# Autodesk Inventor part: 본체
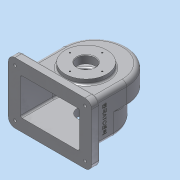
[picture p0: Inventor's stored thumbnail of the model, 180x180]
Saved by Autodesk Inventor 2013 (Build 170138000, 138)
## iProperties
Created: 2017-11
Part Number: 본체
Material: 알루미늄 6061
Document SubType Name: Modeling
Designer: dgall
Density: 2.71 g/cm^3
Mass: 1079.49 g
Surface Area: 1182.07 cm^2
Volume: 398.334 cm^3
Author: dgall
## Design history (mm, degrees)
sketch "스케치1"
  geometry: L1 (-58, 0)-(-58, -80); L2 (-58, -80)-(58, -80); L3 (58, -80)-(58, 0); A1 r 58 centre (0, 0) between (-58, 0) and (58, 0); 1 further point
  constraints: 6 end point, 2 point on circle, 2 tangent, 2 vertical, 1 centre point, 1 coincident, 1 perpendicular
  dimensions: "d0" = 58 radius of A1; "d1" = 80 distance of L1.start L1.end
extrude "돌출1" new body sketch "스케치1" distance "d2" = 38; taper "d3" = 0 deg
sketch "스케치2"
  geometry: L1 (58, 0)-(58, -80) reference; L2 (-58, -80)-(-58, 0) reference; L3 (58, -80)-(-58, -80) reference; L4 (-58, -23)-(-58, -80); L5 (58, -80)-(-58, -80); L6 (58, -80)-(58, -23); A1 r 58 centre (0, 0) between (58, 0) and (-58, 0) reference; A2 r 58 centre (0, -23) between (10.724, -80) and (-10.724, -80)
  constraints: 6 end point, 4 point on circle, 4 point on line, 2 collinear, 1 centre point, 1 vertical alignment
  dimensions: "d4" = 58 radius of A2; "d5" = 57 distance from line of L3 A2.centre
extrude "돌출2" join sketch "스케치2" distance "d6" = 38; taper "d7" = 0 deg
feature "쉘1" dims "d8" = 5
sketch "스케치3"
  geometry: L1 (-58, -80)-(58, -80) reference; C1 r 37.5 at (0, -15); A1 r 58 centre (0, 0) between (58, 0) and (-58, 0) reference
  constraints: 1 centre point, 1 vertical alignment
  dimensions: "d9" = 75 diameter of C1; "d10" = 65 distance from line of L1 C1.centre
extrude "돌출3" join sketch "스케치3" distance "d11" = 9; taper "d12" = 0 deg
sketch "스케치4"
  geometry: L1 (-58, -80)-(58, -80) reference; C1 r 31 at (0, -15); A1 r 58 centre (0, -23) between (58, -23) and (-58, -23) reference; 1 further point
  constraints: 1 centre point, 1 vertical alignment
  dimensions: "d13" = 62 diameter of C1; "d14" = 65 distance from line of L1 C1.centre
extrude "돌출4" join sketch "스케치4" distance "d15" = 10; taper "d16" = 0 deg
sketch "스케치5"
  geometry: C1 r 37.5 at (0, 0) reference; C2 r 16 at (0, 0); 1 further point
  constraints: 1 centre point, 1 coincident
  dimensions: "d17" = 32 diameter of C2
extrude "돌출5" cut sketch "스케치5" stored distance "d18" = 10; taper "d19" = 0 deg
sketch "스케치6" dims "d20" = 58
  geometry: C1 r 37.5 at (0, 0) reference; 3 further points
  constraints: 2 vertical alignment, 1 coincident, 2 other
hole "구멍1" sketch "스케치6" at (0, 29) diameter "d21" = 2.459; stored, may be unused: countersink angle "d25" = 90 deg, drill point angle "d27" = 118 deg; dims "d22" = 6, "d23" = 4, "d24" = 2, "d26" = 8
sketch "스케치7" dims "d31" = 52
  geometry: C1 r 16 at (0, 0) reference; C2 r 31 at (0, 0) reference; 3 further points
  constraints: 2 vertical alignment, 1 coincident, 2 other
hole "구멍2" sketch "스케치7" at (0, 26) diameter "d32" = 2.459; stored, may be unused: countersink angle "d36" = 90 deg, drill point angle "d38" = 118 deg; dims "d33" = 6, "d34" = 4, "d35" = 2, "d37" = 8
chamfer "모따기1" distance "d42" = 1; stored, may be unused: second distance "d43" = 2, angle "d44" = 45 deg
sketch "스케치8"
  geometry: L1 (-17, 17)-(133, 17); L2 (133, 17)-(133, -93); L3 (133, -93)-(-17, -93); L4 (-17, -93)-(-17, 17); L5 (116, -38)-(0, -38) reference; L6 (0, 0)-(116, 0); L7 (116, 0)-(116, -76); L8 (116, -76)-(0, -76); L9 (0, -76)-(0, 0); 4 further points
  constraints: 16 end point, 4 parallel, 3 midpoint, 2 horizontal, 2 perpendicular, 1 horizontal alignment, 1 vertical alignment
  dimensions: "d45" = 150 distance of L1.start L1.end; "d47" = 110 distance of L1.end L2.end
extrude "돌출6" join sketch "스케치8" distance "d48" = 15; taper "d49" = 0 deg
fillet "모깎기1" dims "d50" = 12
sketch "스케치9"
  geometry: A1 r 12 centre (-5, -5) between (-17, -5) and (-5, -17) reference; A2 r 12 centre (121, -5) between (121, -17) and (133, -5) reference; A3 r 12 centre (121, 81) between (133, 81) and (121, 93) reference; A4 r 12 centre (-5, 81) between (-5, 93) and (-17, 81) reference; 5 further points
  constraints: 4 coincident
hole "구멍3" sketch "스케치9" at (-5, 81), (-5, -5), (121, -5), (121, 81) diameter "d51" = 5; stored, may be unused: countersink angle "d55" = 90 deg, drill point angle "d57" = 118 deg; dims "d52" = 6, "d53" = 12, "d54" = 5, "d56" = 8
node "작업 평면1"
sketch "스케치11"
  geometry: L1 (-121, 55)-(-121, 93) reference; L2 (-121, 55)-(-5, 55) reference; L3 (-5, 55)-(-5, 93) reference; L4 (-121, 93)-(-5, 93) reference; L5 (12, 12)-(12, 98) reference; C1 r 6 at (-63, 74); 2 further points
  constraints: 1 centre point, 1 horizontal alignment, 1 midpoint
  dimensions: "d59" = 12 diameter of C1; "d60" = 75 distance from line of C1.centre L5
extrude "돌출7" join sketch "스케치11" stored distance "d61" = 15; taper "d62" = 0 deg
hole "구멍4" diameter "d65" = 4.459; stored, may be unused: countersink angle "d69" = 90 deg, drill point angle "d71" = 118 deg; dims "d63" = 10, "d64" = 10, "d66" = 6, "d67" = 12, "d68" = 5, "d70" = 8
fillet "모깎기2" dims "d72" = 8
fillet "모깎기3" dims "d73" = 3
fillet "모깎기4" dims "d74" = 3
fillet "모깎기5" dims "d75" = 3
fillet "모깎기6" dims "d76" = 3
fillet "모깎기7" dims "d77" = 3
fillet "모깎기8" dims "d78" = 3
sketch "스케치12"
  geometry: L1 (-40, -57)-(46, -57) reference; L2 (-35, 23)-(-35, -39) reference; 2 further points
  constraints: 1 other
  dimensions: "d79" = 40 distance from line of L1 point (3, -17); "d80" = 38 distance from line of L2 point (3, -17)
feature "엠보싱1" sketch "스케치12" dims "d0" = 58, "d1" = 80, "d81" = 0.5, "d82" = 0
node "솔리드1"
pattern_circular "원형 패턴1" dims angle "d29" = 360 deg
pattern_circular "원형 패턴2" dims angle "d40" = 360 deg
node "투영된 루프1"
other parameters: "d58" = -144
